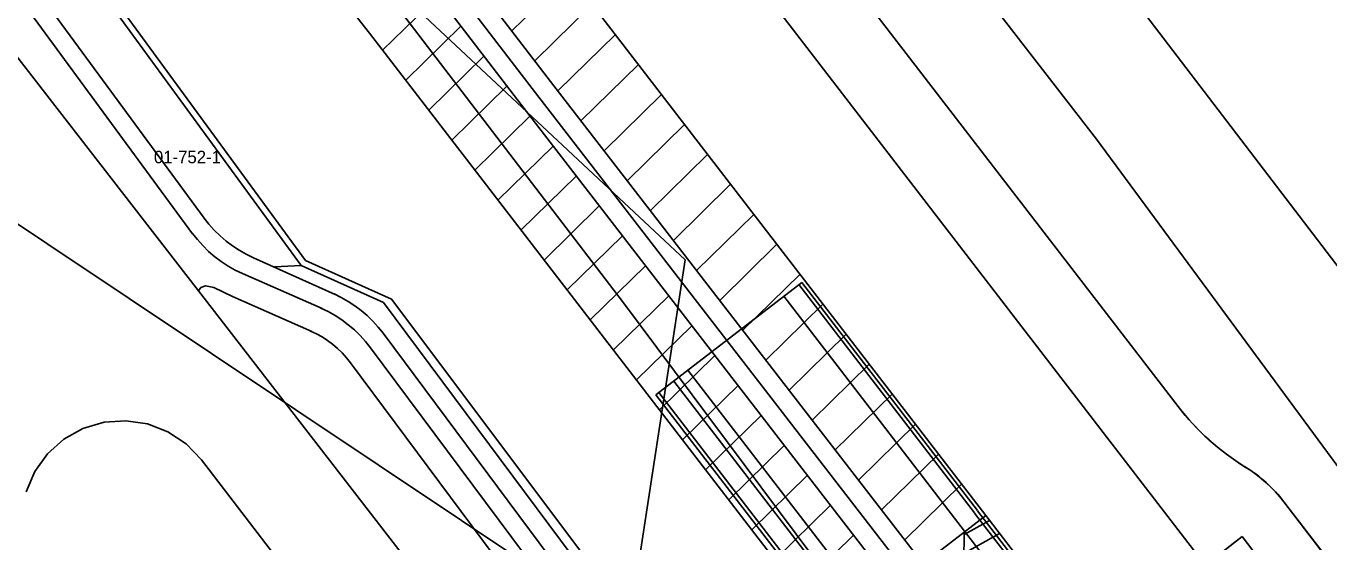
# Model space of a CAD drawing. Extents: x 413946 to 415528, y 4453939 to 4454944.
# Drawn here: x 414871.3 to 414975.4, y 4454271.8 to 4454313 of the extents above; entities that cross this region are included whole.
import ezdxf

# ---------------------------------------------------------------- set-up
doc = ezdxf.new("R2010")
doc.units = 0
for name, color, linetype in [('0_KADASTRO', 7, 'Continuous'), ('Level 11', 7, 'Continuous'), ('Level 53', 7, 'Continuous'), ('Level 62', 7, 'Continuous')]:
    doc.layers.add(name, color=color, linetype=linetype)

msp = doc.modelspace()

# ---------------------------------------------------------------- linework, layer by layer
at = {"layer": '0_KADASTRO'}
msp.add_lwpolyline([(414876.31, 4454338.87), (414923.97, 4454294.31), (414919.42, 4454264.59), (414859.64, 4454304.49), (414841.63, 4454343.32), (414867.99, 4454328.24)], close=True, dxfattribs=at)
at = {"layer": 'Level 11'}
msp.add_lwpolyline([(414904.14, 4454365.18), (414921.72, 4454349.28), (414956.84, 4454303.94), (415043.92, 4454185.88), (415017.18, 4454160.26), (414989.9, 4454195.56), (414957.79, 4454239), (414918.97, 4454290.97), (414874.38, 4454349.28)], dxfattribs=at)
at = {"layer": 'Level 53'}
for p, q in [((414912.02, 4454320.57), (414947.99, 4454273.88)), ((414910.12, 4454312.58), (414914.71, 4454317.08)), ((414899.8, 4454311.04), (414904.21, 4454315.35)), ((414911.96, 4454310.18), (414916.55, 4454314.69)), ((414901.65, 4454308.65), (414906.05, 4454312.96)), ((414913.8, 4454307.79), (414918.4, 4454312.29)), ((414899.74, 4454311.12), (414935.71, 4454264.43)), ((414903.49, 4454306.25), (414907.89, 4454310.56)), ((414915.65, 4454305.4), (414920.24, 4454309.9)), ((414905.33, 4454303.86), (414909.73, 4454308.17)), ((414917.5, 4454303.01), (414922.08, 4454307.51)), ((414907.18, 4454301.46), (414911.57, 4454305.77)), ((414919.35, 4454300.62), (414923.93, 4454305.11)), ((414909.02, 4454299.07), (414913.42, 4454303.38)), ((414921.2, 4454298.23), (414925.77, 4454302.72)), ((414910.86, 4454296.68), (414915.27, 4454300.99)), ((414923.04, 4454295.84), (414927.61, 4454300.33)), ((414912.71, 4454294.28), (414917.11, 4454298.6)), ((414924.89, 4454293.45), (414929.46, 4454297.93)), ((414914.55, 4454291.89), (414918.96, 4454296.21)), ((414926.74, 4454291.06), (414931.3, 4454295.54)), ((414916.4, 4454289.5), (414920.81, 4454293.82)), ((414928.59, 4454288.67), (414933.15, 4454293.14)), ((414918.24, 4454287.1), (414922.66, 4454291.43)), ((414930.43, 4454286.28), (414934.99, 4454290.75)), ((414920.08, 4454284.71), (414924.5, 4454289.04)), ((414932.28, 4454283.88), (414936.84, 4454288.36)), ((414921.93, 4454282.32), (414926.35, 4454286.65)), ((414934.13, 4454281.5), (414938.68, 4454285.96)), ((414923.77, 4454279.92), (414928.2, 4454284.26)), ((414935.97, 4454279.11), (414940.52, 4454283.57)), ((414925.61, 4454277.53), (414930.04, 4454281.87)), ((414937.82, 4454276.71), (414942.37, 4454281.17)), ((414927.46, 4454275.14), (414931.89, 4454279.48)), ((414939.67, 4454274.32), (414944.21, 4454278.78)), ((414929.3, 4454272.74), (414933.74, 4454277.09)), ((414941.52, 4454271.93), (414946.05, 4454276.39)), ((414931.14, 4454270.35), (414935.59, 4454274.7)), ((414947.99, 4454273.88), (414935.71, 4454264.43)), ((414947.99, 4454273.88), (414991.44, 4454217.47)), ((414946.26, 4454272.35), (414948.29, 4454273.49)), ((414932.99, 4454267.96), (414937.43, 4454272.31)), ((414946.24, 4454270.85), (414949.09, 4454272.45))]:
    msp.add_line(p, q, dxfattribs=at)
for points in [[(414423.97, 4454943.96), (414424.74, 4454942.96), (414572.06, 4454750.76), (414639.34, 4454663.46), (414685.25, 4454604.44), (414748.18, 4454522.38), (414789.33, 4454468.63), (414859.79, 4454378.08), (414913.22, 4454308.55), (414942.99, 4454270.03)], [(414421.52, 4454942.22), (414422.36, 4454941.13), (414569.68, 4454748.94), (414636.96, 4454661.62), (414682.88, 4454602.6), (414745.8, 4454520.56), (414786.96, 4454466.79), (414857.41, 4454376.24), (414910.84, 4454306.72), (414940.61, 4454268.2)], [(414423.78, 4454941.75), (414570.87, 4454749.85), (414638.15, 4454662.54), (414684.06, 4454603.52), (414746.99, 4454521.47), (414788.14, 4454467.71), (414858.6, 4454377.16), (414912.03, 4454307.64), (414941.8, 4454269.12)], [(414946.21, 4454267.85), (414946.26, 4454272.54)]]:
    msp.add_lwpolyline(points, dxfattribs=at)
msp.add_arc((416088.05, 4455226.49), 1500, 215.65019, 217.60731, dxfattribs=at)
at = {"layer": 'Level 62'}
for p, q in [((414925.88, 4454331.25), (414963.38, 4454282.58)), ((414866.79, 4454330.12), (414893.3, 4454293.84)), ((414867.28, 4454330.3), (414893.63, 4454294.25)), ((414921.13, 4454327.59), (415036.06, 4454178.39)), ((414885.54, 4454297.63), (414868.02, 4454321.48)), ((414994.03, 4454270.32), (414957, 4454318.82)), ((414896.02, 4454291.53), (414889.49, 4454294.46)), ((414893.3, 4454293.84), (414891.16, 4454293.75)), ((414899.88, 4454290.9), (414893.3, 4454293.84)), ((414900.51, 4454291.17), (414893.63, 4454294.25)), ((414894.96, 4454290.4), (414888.61, 4454293.2)), ((414933.29, 4454292.5), (414921.63, 4454283.52)), ((414933.29, 4454292.5), (414947.33, 4454274.27)), ((414894.15, 4454288.57), (414887.81, 4454291.37)), ((414931.85, 4454291.39), (415004.43, 4454197.17)), ((414933.05, 4454292.32), (414947.09, 4454274.09)), ((414899.88, 4454290.9), (414930.55, 4454249.74)), ((414900.51, 4454291.17), (414961.03, 4454210.6)), ((414899.85, 4454288.43), (414925.07, 4454254.59)), ((414898.84, 4454287.27), (414923.62, 4454254.02)), ((414897.24, 4454286.08), (414922.84, 4454251.72)), ((414924.19, 4454285.49), (414996.75, 4454191.25)), ((414923.06, 4454284.62), (414995.64, 4454190.4)), ((414921.63, 4454283.52), (414935.67, 4454265.29)), ((414921.87, 4454283.71), (414935.91, 4454265.48)), ((414971.81, 4454274.97), (414998.14, 4454240.81)), ((414971.82, 4454274.97), (414998.14, 4454240.81)), ((414947.1, 4454274.07), (414958.64, 4454259.09)), ((414947.34, 4454274.25), (414958.88, 4454259.27)), ((414968.49, 4454272.19), (414965.95, 4454270.24)), ((414966.27, 4454270.48), (414968.49, 4454272.19)), ((414978.1, 4454259.71), (414968.49, 4454272.19)), ((414968.49, 4454272.19), (414974.34, 4454264.59))]:
    msp.add_line(p, q, dxfattribs=at)
for points in [[(414852.76, 4454333.52), (414862.47, 4454320.98), (414885.08, 4454291.81), (414922.93, 4454242.92), (414957.19, 4454198.7), (415004.03, 4454138.23)], [(414884.62, 4454296.38), (414866.62, 4454320.84)], [(414885.52, 4454297.66), (414885.92, 4454297.15), (414886.35, 4454296.67), (414886.81, 4454296.22), (414887.3, 4454295.8), (414887.81, 4454295.41), (414888.35, 4454295.06), (414888.91, 4454294.74), (414889.49, 4454294.46)], [(414884.59, 4454296.42), (414885, 4454295.91), (414885.43, 4454295.43), (414885.9, 4454294.97), (414886.39, 4454294.55), (414886.91, 4454294.16), (414887.46, 4454293.8), (414888.03, 4454293.48), (414888.61, 4454293.2)], [(414887.81, 4454291.37), (414886.31, 4454292.08), (414885.65, 4454292.22), (414885.29, 4454292.09), (414885.08, 4454291.81)], [(414899.86, 4454288.42), (414899.46, 4454288.92), (414899.03, 4454289.39), (414898.58, 4454289.84), (414898.09, 4454290.25), (414897.58, 4454290.63), (414897.05, 4454290.98), (414896.5, 4454291.3), (414895.93, 4454291.57)], [(414898.84, 4454287.27), (414898.44, 4454287.77), (414898.01, 4454288.25), (414897.55, 4454288.7), (414897.06, 4454289.11), (414896.54, 4454289.5), (414896, 4454289.85), (414895.44, 4454290.17), (414894.86, 4454290.44)], [(414897.24, 4454286.07), (414896.92, 4454286.48), (414896.57, 4454286.86), (414896.2, 4454287.22), (414895.81, 4454287.55), (414895.4, 4454287.86), (414894.97, 4454288.14), (414894.52, 4454288.39), (414894.05, 4454288.61)], [(414963.37, 4454282.58), (414963.94, 4454281.87), (414964.54, 4454281.19), (414965.17, 4454280.54), (414965.83, 4454279.92), (414966.52, 4454279.33), (414967.23, 4454278.77), (414967.97, 4454278.24), (414968.73, 4454277.75)], [(414885.32, 4454278.32), (414884.11, 4454279.59), (414882.65, 4454280.56), (414881.02, 4454281.19), (414879.29, 4454281.45), (414877.54, 4454281.33), (414875.86, 4454280.83), (414874.33, 4454279.97), (414873.03, 4454278.81), (414872, 4454277.39), (414871.31, 4454275.78)], [(415010.57, 4454113.86), (414937.73, 4454209.95), (414885.32, 4454278.32)], [(414971.82, 4454274.97), (414971.49, 4454275.38), (414971.14, 4454275.77), (414970.78, 4454276.14), (414970.4, 4454276.5), (414970.01, 4454276.84), (414969.6, 4454277.16), (414969.17, 4454277.47), (414968.73, 4454277.75)]]:
    msp.add_lwpolyline(points, dxfattribs=at)
for centre, radius, start, end in [((414979.22, 4454294.78), 20, 217.6073, 238.3887), ((414962.71, 4454267.96), 11.5, 37.6073, 58.3886)]:
    msp.add_arc(centre, radius, start, end, dxfattribs=at)

# ---------------------------------------------------------------- texts
at = {"layer": '0_KADASTRO'}
msp.add_text('01-752-1', height=1, dxfattribs=at).set_placement((414881.53, 4454302.01))

doc.saveas('drawing.dxf')
